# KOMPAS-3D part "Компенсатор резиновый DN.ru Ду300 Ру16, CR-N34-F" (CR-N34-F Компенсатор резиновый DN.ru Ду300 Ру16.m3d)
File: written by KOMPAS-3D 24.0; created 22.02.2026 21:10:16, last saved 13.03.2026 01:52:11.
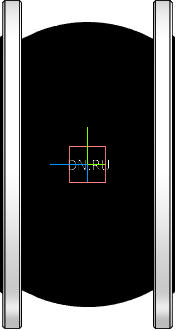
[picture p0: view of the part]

Document properties: Автор: DN.RU; Полное имя файла: CR-N34-F Компенсатор резиновый DN.ru Ду300 Ру16.cdw

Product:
- Body: Твердое тело2  | qty 1
    Масса: 101.598119
- Part/product: Компенсатор резиновый DN.ru Ду300 Ру16  | designation CR-N34-F
    Масса: 30
    Раздел спецификации: Прочие изделия
    Форматы листов документа: A2
    Комментарий: D140-02109
    Примечание: D140-02109
    additional columns: Типовые

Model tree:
1. Твердое тело2  (labels: Твердое тело2)

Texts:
  CR-N34-F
